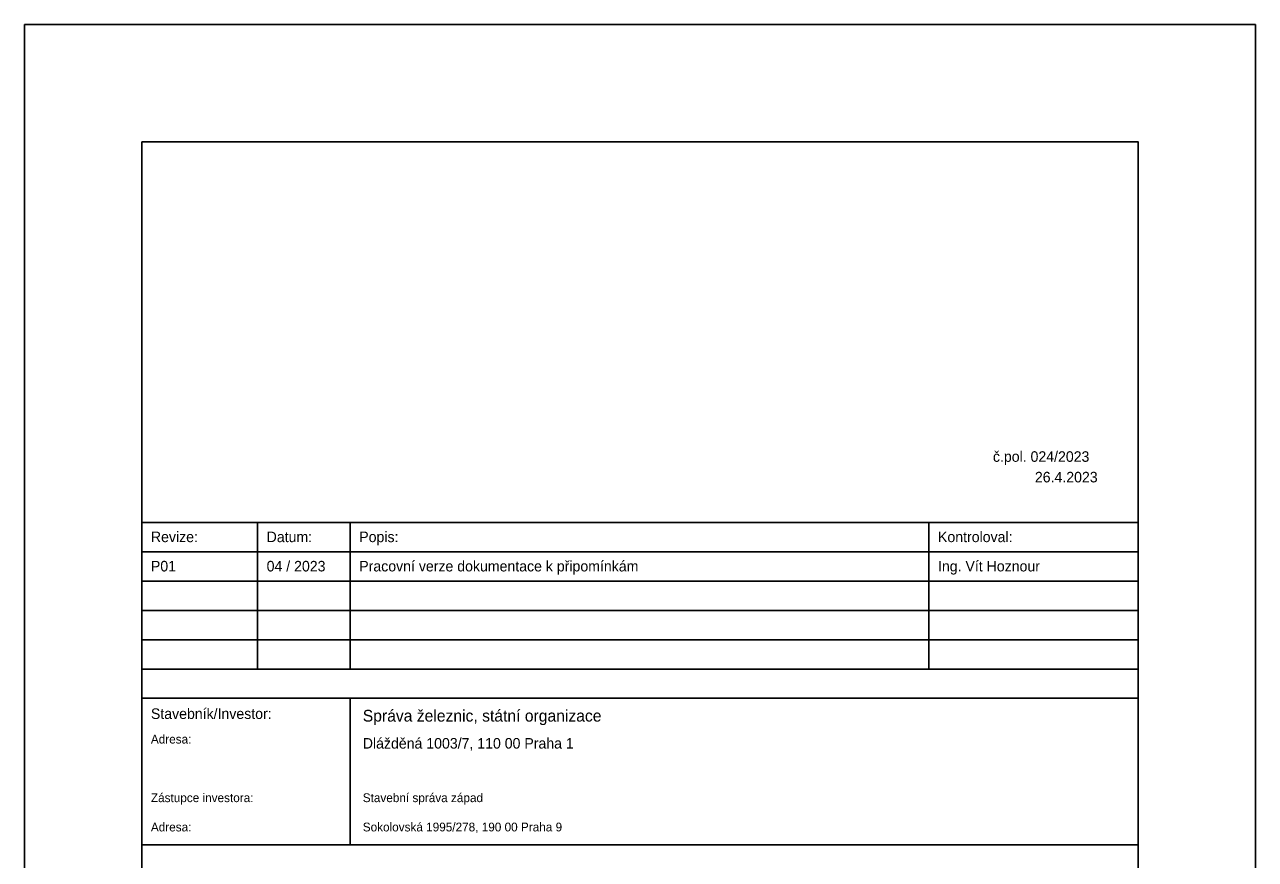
# Model space of a CAD drawing. Extents: x 70 to 433, y -123 to 195.
# Drawn here: x 70 to 280, y 31.5 to 174 of the extents above; entities that cross this region are included whole.
import ezdxf

# ---------------------------------------------------------------- set-up
doc = ezdxf.new("R2010")
doc.units = 0
doc.layers.add('Popisove_pole', color=7, linetype='Continuous')
doc.layers.add('SO 11-10-01_popisove_pole', color=7, linetype='Continuous')

msp = doc.modelspace()

# ---------------------------------------------------------------- linework, layer by layer
at = {"layer": 'SO 11-10-01_popisove_pole'}
for p, q in [((109.7, 63.95), (109.7, 88.95)), ((125.5, 63.95), (125.5, 88.95)), ((224.25, 63.95), (224.25, 88.95)), ((89.95, 83.95), (259.95, 83.95)), ((89.95, 78.95), (259.95, 78.95)), ((89.95, 73.95), (259.95, 73.95)), ((89.95, 68.95), (259.95, 68.95)), ((125.5, 33.95), (125.5, 58.95))]:
    msp.add_line(p, q, dxfattribs=at)
for points in [[(279.95, -123.05), (279.95, 173.95), (69.95, 173.95), (69.95, -123.05)], [(89.95, 153.95), (259.95, 153.95), (259.95, -106.05), (89.95, -106.05)], [(89.95, 88.95), (259.95, 88.95), (259.95, 63.95), (89.95, 63.95)], [(89.95, 58.95), (259.95, 58.95), (259.95, 33.95), (89.95, 33.95)]]:
    msp.add_lwpolyline(points, close=True, dxfattribs=at)

# ---------------------------------------------------------------- texts
at = {"layer": 'Popisove_pole'}
for s, p in [('č.pol. 024/2023', (235.17, 99.32)), ('26.4.2023', (242.33, 95.81))]:
    msp.add_text(s, height=1.8, rotation=360, dxfattribs=at).set_placement(p)
at = {"layer": 'SO 11-10-01_popisove_pole'}
for s, height, p in [('Revize:', 1.8, (91.5, 85.61)), ('Datum:', 1.8, (111.25, 85.61)), ('Popis:', 1.8, (127.05, 85.61)), ('Kontroloval:', 1.8, (225.8, 85.61)), ('P01', 1.8, (91.5, 80.61)), ('04 / 2023', 1.8, (111.25, 80.61)), ('Pracovní verze dokumentace k připomínkám', 1.8, (127.05, 80.61)), ('Ing. Vít Hoznour', 1.8, (225.8, 80.61)), ('Stavebník/Investor:', 1.8, (91.5, 55.43)), ('Správa železnic, státní organizace', 2, (127.65, 54.98)), ('Adresa:', 1.5, (91.5, 51.23)), ('Dlážděná 1003/7, 110 00 Praha 1', 1.8, (127.65, 50.37)), ('Zástupce investora:', 1.5, (91.5, 41.23)), ('Stavební správa západ', 1.5, (127.65, 41.23)), ('Adresa:', 1.5, (91.5, 36.23)), ('Sokolovská 1995/278, 190 00 Praha 9', 1.5, (127.65, 36.23))]:
    msp.add_text(s, height=height, rotation=360, dxfattribs=at).set_placement(p)

doc.saveas('drawing.dxf')
